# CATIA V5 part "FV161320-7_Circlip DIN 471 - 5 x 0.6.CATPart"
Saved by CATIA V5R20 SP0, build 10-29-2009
Part number: FV161320-7_Circlip DIN 471 - 5 x 0.6
Revision: ANY
Definition: UNKNOWN
Nomenclature: FV161320-7_Circlip DIN 471 - 5 x 0.6
Source: Unknown
Bounding box of the stored display mesh (mm): x -3.167 to 3.167, y -4.898 to 3.345, z -0.6 to 0
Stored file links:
  C:\Users\Utente\Desktop\IO LAVORO\3D X SITO CF\CUMSA\3D files FV\FV 161320\FV161320-7_Circlip DIN 471 - 5 x 0.6.CATPart
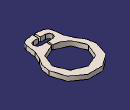
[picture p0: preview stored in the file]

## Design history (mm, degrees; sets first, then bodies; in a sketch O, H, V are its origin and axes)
Body1 "Notch" (main body)
  Solid1: solid without history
